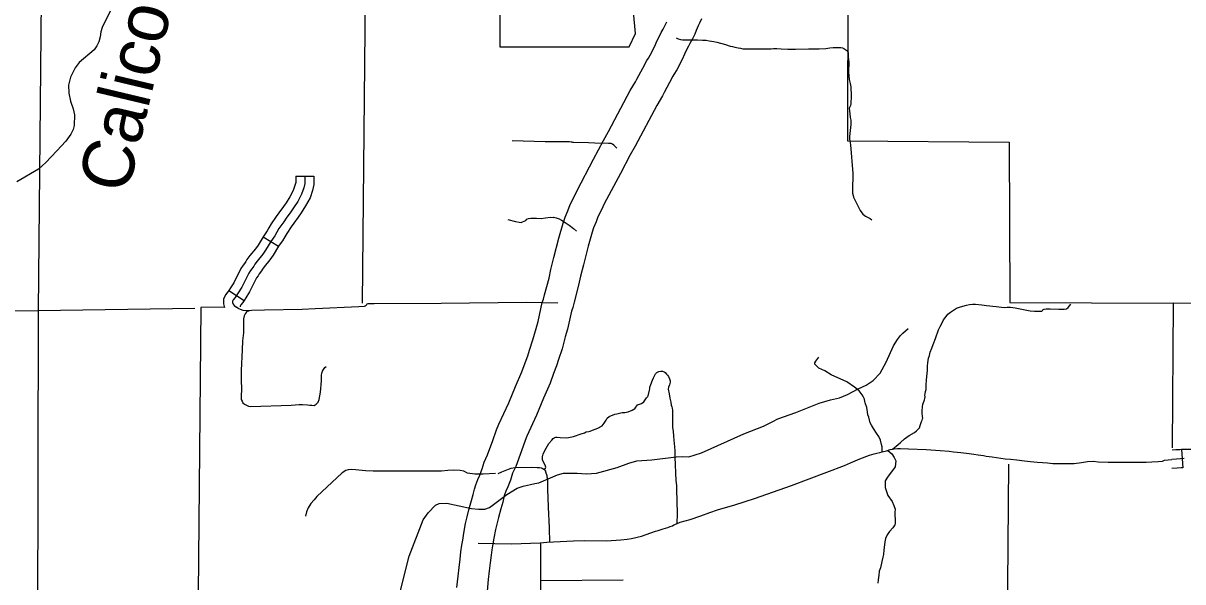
# Model space of a CAD drawing. Extents: x 1377389 to 1380723, y 1168351 to 1170484.
# Drawn here: x 1378680.8 to 1378871.6, y 1168997.5 to 1169089.4 of the extents above; entities that cross this region are included whole.
import ezdxf

# ---------------------------------------------------------------- set-up
doc = ezdxf.new("R2010")
doc.units = 0
doc.layers.add('B_Fill', color=7, linetype='Continuous')

msp = doc.modelspace()

# ---------------------------------------------------------------- linework, layer by layer
at = {"layer": 'B_Fill'}
for p, q in [((1378725.61, 1169064.2), (1378728.61, 1169064.2)), ((1378720.23, 1169054.24), (1378722.8, 1169052.7)), ((1378714.6, 1169045.4), (1378717.12, 1169043.77)), ((1378871.37, 1169019.22), (1378871.59, 1169016.23))]:
    msp.add_line(p, q, dxfattribs=at)
for points in [[(1378737.66, 1169202.93), (1378737.6, 1169150.04), (1378736.52, 1169043.33)], [(1378842.99, 1169154.28), (1378843.04, 1169149.86), (1378843.04, 1169123.02), (1378816.55, 1169123.12), (1378816.4, 1169069.98), (1378843.01, 1169069.78), (1378843.12, 1169043.4)], [(1378684.26, 1169150.09), (1378683.24, 1169042.11)], [(1378695.06, 1169091.31), (1378693.76, 1169088.66), (1378693.52, 1169087.95), (1378693.44, 1169087.09), (1378693.23, 1169086.27), (1378692.89, 1169085.64), (1378692.45, 1169084.99), (1378689.96, 1169082.87), (1378689.32, 1169082), (1378688.57, 1169080.5), (1378688.21, 1169079.15), (1378688.28, 1169077.83), (1378688.56, 1169076.55), (1378689.01, 1169075.26), (1378689.19, 1169074.27), (1378689.13, 1169072.52), (1378689.01, 1169071.86), (1378688.59, 1169071.09), (1378687.77, 1169069.95), (1378686.31, 1169068.38), (1378684.5, 1169066.46), (1378683.27, 1169065.37), (1378679.7, 1169063.29)], [(1378780.67, 1169078.26), (1378781.52, 1169079.69), (1378781.72, 1169080.16), (1378782.71, 1169081.97), (1378783.37, 1169083.21), (1378783.64, 1169083.61), (1378783.94, 1169084.12), (1378784.7, 1169085.57), (1378785.06, 1169086.39), (1378785.49, 1169087.23), (1378785.76, 1169087.85), (1378786.07, 1169088.4), (1378786.45, 1169089.12), (1378786.7, 1169089.6)], [(1378792.36, 1169090.09), (1378792.04, 1169089.34), (1378791.83, 1169088.92), (1378791.67, 1169088.54), (1378791.5, 1169088.15), (1378791.27, 1169087.54), (1378790.88, 1169086.81), (1378790.47, 1169086.01), (1378790.24, 1169085.6), (1378790, 1169085.08), (1378789.58, 1169084.24), (1378789.21, 1169083.41), (1378788.31, 1169081.68), (1378787.85, 1169080.92), (1378787.65, 1169080.62), (1378787.11, 1169079.61), (1378786.22, 1169077.96), (1378785.98, 1169077.41), (1378785.03, 1169075.81)], [(1378788.2, 1169086.93), (1378788.57, 1169086.8), (1378788.92, 1169086.7), (1378789.27, 1169086.63), (1378789.82, 1169086.61), (1378791, 1169086.61), (1378791.74, 1169086.61), (1378792.53, 1169086.59), (1378793.15, 1169086.54), (1378793.64, 1169086.47), (1378794.03, 1169086.41), (1378794.42, 1169086.33), (1378794.89, 1169086.22), (1378796.36, 1169085.83), (1378797.13, 1169085.6), (1378797.5, 1169085.52), (1378797.89, 1169085.41), (1378798.42, 1169085.3), (1378798.82, 1169085.23), (1378799.21, 1169085.16), (1378799.79, 1169085.13), (1378801.11, 1169085.13), (1378802.29, 1169085.14), (1378803.84, 1169085.16), (1378804.23, 1169085.18), (1378804.8, 1169085.18), (1378805.48, 1169085.14), (1378806.61, 1169085.07), (1378807.83, 1169085.11), (1378809.99, 1169085.13), (1378811.74, 1169085.14), (1378812.85, 1169085.2), (1378813.48, 1169085.29), (1378814.08, 1169085.34), (1378814.72, 1169085.36), (1378815.03, 1169085.36), (1378815.3, 1169085.34), (1378815.58, 1169085.29), (1378815.79, 1169085.2), (1378815.97, 1169085.11), (1378816.16, 1169084.98), (1378816.28, 1169084.88), (1378816.37, 1169084.81), (1378816.4, 1169084.79), (1378816.41, 1169084.77), (1378816.42, 1169084.76), (1378816.44, 1169084.71)], [(1378816.44, 1169084.71), (1378816.47, 1169084.64), (1378816.52, 1169084.52), (1378816.54, 1169084.39), (1378816.53, 1169083.85), (1378816.63, 1169082.96), (1378816.58, 1169081.29), (1378816.69, 1169080.12), (1378816.88, 1169079.45), (1378816.97, 1169078.89), (1378817.04, 1169077.41), (1378816.95, 1169076.11), (1378816.9, 1169075.83), (1378816.75, 1169075.5), (1378816.68, 1169075.32), (1378816.76, 1169075.02), (1378816.83, 1169073.86), (1378816.94, 1169073.43), (1378816.99, 1169073.19), (1378816.94, 1169072.71), (1378816.73, 1169070.72), (1378816.73, 1169070.26), (1378816.79, 1169069.98)], [(1378752.15, 1168996.53), (1378752.33, 1168998.4), (1378752.49, 1168999.84), (1378752.65, 1169001.19), (1378752.8, 1169002.4), (1378752.92, 1169003.49), (1378753.09, 1169004.33), (1378753.3, 1169005.5), (1378753.57, 1169007.06), (1378753.83, 1169008.15), (1378754.12, 1169009.34), (1378754.53, 1169010.83), (1378754.82, 1169011.81), (1378755.02, 1169012.73), (1378755.25, 1169013.4), (1378755.56, 1169014.29), (1378755.91, 1169015.01), (1378756.18, 1169015.77), (1378756.28, 1169016.08), (1378756.64, 1169017.18), (1378757.18, 1169018.37), (1378758.06, 1169020.72), (1378758.67, 1169022.48), (1378759.05, 1169023.43), (1378760.66, 1169026.92), (1378761.79, 1169029.61), (1378762.82, 1169032.02), (1378763.37, 1169033.51), (1378763.79, 1169034.63), (1378764.09, 1169035.58), (1378764.65, 1169037.26), (1378765.17, 1169039.13), (1378765.51, 1169040.27), (1378766.18, 1169043.39), (1378766.39, 1169043.98), (1378766.55, 1169044.7), (1378767.31, 1169047.43), (1378767.61, 1169048.86), (1378768.1, 1169050.84), (1378768.89, 1169053.98), (1378769.63, 1169056.49), (1378769.95, 1169057.43), (1378770.39, 1169058.52), (1378770.77, 1169059.52), (1378771.43, 1169060.82), (1378771.91, 1169061.86), (1378774.64, 1169066.99), (1378776.27, 1169070.08), (1378777.08, 1169071.52), (1378780.67, 1169078.26)], [(1378785.03, 1169075.81), (1378781.47, 1169069.12), (1378780.66, 1169067.68), (1378779.05, 1169064.65), (1378776.39, 1169059.64), (1378775.93, 1169058.64), (1378775.34, 1169057.48), (1378775.05, 1169056.7), (1378774.64, 1169055.69), (1378774.39, 1169054.97), (1378773.72, 1169052.66), (1378772.95, 1169049.63), (1378772.49, 1169047.74), (1378772.17, 1169046.24), (1378771.41, 1169043.48), (1378771.2, 1169042.57), (1378771, 1169042.01), (1378770.36, 1169039.02), (1378769.97, 1169037.75), (1378769.44, 1169035.81), (1378768.85, 1169034.03), (1378768.52, 1169032.99), (1378768.05, 1169031.76), (1378767.46, 1169030.17), (1378766.4, 1169027.66), (1378765.23, 1169024.91), (1378763.65, 1169021.44), (1378763.35, 1169020.72), (1378762.76, 1169019.03), (1378761.81, 1169016.46), (1378761.3, 1169015.35), (1378761.04, 1169014.56), (1378760.93, 1169014.19), (1378760.52, 1169013.07), (1378760.19, 1169012.38), (1378759.98, 1169011.76), (1378759.84, 1169011.38), (1378759.67, 1169010.57), (1378759.34, 1169009.46), (1378758.96, 1169008.07), (1378758.68, 1169006.96), (1378758.47, 1169006.06), (1378758.22, 1169004.64), (1378758.01, 1169003.4), (1378757.87, 1169002.72), (1378757.77, 1169001.83), (1378757.61, 1169000.58), (1378757.46, 1168999.27), (1378757.3, 1168997.88), (1378757.12, 1168995.93)], [(1378778.43, 1169068.82), (1378777.94, 1169069.29), (1378777.73, 1169069.47), (1378777.54, 1169069.55), (1378777.38, 1169069.58), (1378777.1, 1169069.58), (1378774.84, 1169069.65), (1378773.78, 1169069.66), (1378771.33, 1169069.75), (1378771.22, 1169069.76), (1378771.11, 1169069.77), (1378770.95, 1169069.81), (1378770.69, 1169069.85), (1378770.35, 1169069.87), (1378769.46, 1169069.83), (1378766.64, 1169069.85), (1378761.25, 1169069.99)], [(1378816.79, 1169069.98), (1378816.93, 1169069.35), (1378817.29, 1169064.61), (1378817.26, 1169061.82), (1378817.26, 1169061.4), (1378817.32, 1169061.02), (1378817.4, 1169060.72), (1378818.52, 1169058.54), (1378818.92, 1169057.95), (1378819.38, 1169057.61), (1378820.16, 1169057.21), (1378820.42, 1169057)], [(1378725.61, 1169064.2), (1378725.61, 1169063.17), (1378725.49, 1169062.68), (1378725.2, 1169061.86), (1378724.64, 1169060.8), (1378724.02, 1169059.82), (1378723.59, 1169059.22), (1378722.84, 1169058.18), (1378722.4, 1169057.56), (1378721.58, 1169056.37), (1378721.19, 1169055.69)], [(1378727.11, 1169064.2), (1378727.11, 1169063), (1378726.93, 1169062.25), (1378726.58, 1169061.25), (1378725.94, 1169060.05), (1378725.27, 1169058.98), (1378724.8, 1169058.34), (1378724.06, 1169057.31), (1378723.63, 1169056.71), (1378722.85, 1169055.57), (1378722.18, 1169054.4), (1378721.52, 1169053.47)], [(1378728.61, 1169064.2), (1378728.61, 1169062.82), (1378728.38, 1169061.82), (1378727.96, 1169060.65), (1378727.24, 1169059.29), (1378726.51, 1169058.14), (1378726.02, 1169057.46), (1378725.28, 1169056.44), (1378724.86, 1169055.85), (1378724.12, 1169054.77), (1378723.79, 1169054.2)], [(1378760.49, 1169057.06), (1378761.77, 1169056.73), (1378762.39, 1169056.62), (1378762.72, 1169056.6), (1378762.94, 1169056.68), (1378763.19, 1169056.78), (1378763.46, 1169056.93), (1378763.67, 1169057.1), (1378763.92, 1169057.26), (1378764.29, 1169057.3), (1378765.24, 1169057.28), (1378765.98, 1169057.24), (1378766.69, 1169057.32), (1378767.53, 1169057.45), (1378767.99, 1169057.41), (1378768.01, 1169057.43), (1378768.46, 1169057.34), (1378768.96, 1169057.18), (1378769.37, 1169056.97), (1378769.95, 1169056.6), (1378770.59, 1169056.13), (1378771.32, 1169055.57), (1378771.83, 1169055.16)], [(1378721.19, 1169055.69), (1378720.91, 1169055.21), (1378720.23, 1169054.24)], [(1378720.23, 1169054.24), (1378719.41, 1169052.86), (1378718.98, 1169052.27), (1378718.07, 1169051.15), (1378717.58, 1169050.5), (1378717.41, 1169050.17), (1378717.17, 1169049.84), (1378716.96, 1169049.53), (1378716.59, 1169049.01), (1378715.42, 1169046.66), (1378714.87, 1169045.82), (1378714.6, 1169045.4)], [(1378721.52, 1169053.47), (1378720.66, 1169052.03), (1378720.17, 1169051.36), (1378719.25, 1169050.23), (1378718.86, 1169049.71), (1378718.7, 1169049.4), (1378718.4, 1169048.97), (1378718.18, 1169048.67), (1378717.88, 1169048.24), (1378716.72, 1169045.92), (1378716.13, 1169045), (1378715.65, 1169044.26), (1378715.3, 1169043.85), (1378715.2, 1169043.63), (1378715.2, 1169043.43), (1378715.26, 1169043.27), (1378715.3, 1169043.14), (1378715.46, 1169042.94), (1378715.85, 1169042.65)], [(1378723.79, 1169054.2), (1378723.44, 1169053.58), (1378722.74, 1169052.6)], [(1378722.8, 1169052.7), (1378721.91, 1169051.2), (1378721.36, 1169050.44), (1378720.43, 1169049.3), (1378720.13, 1169048.91), (1378719.99, 1169048.62), (1378719.62, 1169048.11), (1378719.41, 1169047.8), (1378719.17, 1169047.46), (1378718.03, 1169045.17), (1378717.39, 1169044.18), (1378717.12, 1169043.77)], [(1378714.6, 1169045.4), (1378714.44, 1169045.15), (1378714.03, 1169044.66), (1378713.7, 1169043.97), (1378713.7, 1169043.17), (1378713.84, 1169042.77), (1378713.9, 1169042.62)], [(1378717.12, 1169043.77), (1378716.91, 1169043.44), (1378716.56, 1169043.03), (1378716.46, 1169042.82), (1378716.46, 1169042.7)], [(1378578.22, 1169041.82), (1378683.24, 1169042.11)], [(1378713.89, 1169042.63), (1378709.98, 1169042.59), (1378709.33, 1168971.91), (1378682.9, 1168971.87), (1378682.95, 1168989.04), (1378655.79, 1168988.68)], [(1378683.24, 1169042.11), (1378683.13, 1168989.64)], [(1378683.24, 1169042.11), (1378709.01, 1169042.47)], [(1378717.7, 1169042.06), (1378717.94, 1169042.07), (1378717.39, 1169042.06), (1378716.96, 1169042.12), (1378716.5, 1169042.24), (1378716.14, 1169042.42), (1378715.85, 1169042.65)], [(1378718.37, 1169042.09), (1378717.94, 1169042.07), (1378717.76, 1169042.03), (1378717.57, 1169041.9), (1378717.47, 1169041.77), (1378717.3, 1169041.57), (1378717.19, 1169041.35), (1378717.11, 1169041.2), (1378717.01, 1169040.72), (1378716.99, 1169040.43), (1378716.99, 1169039.26), (1378717.01, 1169038.44), (1378716.85, 1169037.13), (1378716.77, 1169035.61), (1378716.64, 1169032.22), (1378716.63, 1169031.28), (1378716.61, 1169030.45), (1378716.69, 1169029.33), (1378716.64, 1169027.83), (1378716.64, 1169027.44), (1378716.78, 1169027.17), (1378716.91, 1169026.91), (1378717.17, 1169026.67), (1378717.6, 1169026.48), (1378717.83, 1169026.38), (1378718.2, 1169026.31), (1378724.87, 1169026.54), (1378726.16, 1169026.64), (1378726.72, 1169026.64), (1378727.55, 1169026.58), (1378727.91, 1169026.51), (1378728.27, 1169026.51), (1378728.64, 1169026.48), (1378729, 1169026.71), (1378729.3, 1169027.01), (1378729.46, 1169027.47), (1378729.66, 1169028.66), (1378729.83, 1169030.54), (1378729.83, 1169031.46), (1378729.89, 1169031.78), (1378730.04, 1169032.12), (1378730.19, 1169032.42), (1378730.41, 1169032.7), (1378730.6, 1169032.9)], [(1378768.74, 1169043.28), (1378763.57, 1169043.4), (1378749.54, 1169043.25), (1378738.51, 1169043.19), (1378737.84, 1169043.19), (1378737.5, 1169043.19), (1378737.32, 1169043.13), (1378737.2, 1169042.94), (1378737.04, 1169042.82), (1378736.86, 1169042.76), (1378735.97, 1169042.7), (1378728.79, 1169042.36), (1378726.68, 1169042.24), (1378720.45, 1169042.15), (1378718.37, 1169042.09)], [(1378823.8, 1169019.31), (1378824.73, 1169020.05), (1378825.14, 1169020.4), (1378825.82, 1169021), (1378826.55, 1169021.54), (1378827.43, 1169022.03), (1378827.76, 1169022.31), (1378828.06, 1169022.57), (1378828.24, 1169022.78), (1378828.39, 1169023.16), (1378828.58, 1169023.86), (1378828.68, 1169024.05), (1378828.78, 1169024.26), (1378828.79, 1169024.41), (1378828.76, 1169024.69), (1378828.72, 1169025.2), (1378828.69, 1169025.53), (1378828.72, 1169025.79), (1378828.73, 1169026.05), (1378828.76, 1169026.31), (1378828.82, 1169026.63), (1378828.93, 1169026.98), (1378829.01, 1169027.25), (1378829.06, 1169027.42), (1378829.13, 1169027.63), (1378829.17, 1169027.88), (1378829.16, 1169028.18), (1378829.19, 1169028.42), (1378829.27, 1169028.75), (1378829.37, 1169029.09), (1378829.37, 1169029.49), (1378829.37, 1169029.83), (1378829.39, 1169030.67), (1378829.5, 1169031.74), (1378829.57, 1169032.23), (1378829.59, 1169032.95), (1378829.65, 1169033.5), (1378829.76, 1169034.27), (1378829.9, 1169034.71), (1378830.03, 1169035.26), (1378830.28, 1169035.9), (1378830.5, 1169036.53), (1378830.89, 1169037.47), (1378831.41, 1169038.9), (1378831.65, 1169039.45), (1378831.93, 1169039.94), (1378832.23, 1169040.55), (1378832.64, 1169041.12), (1378832.95, 1169041.48), (1378833.36, 1169041.81), (1378833.85, 1169042.17), (1378834.35, 1169042.47), (1378834.84, 1169042.64), (1378835.37, 1169042.83), (1378836, 1169043), (1378836.49, 1169043.08), (1378836.96, 1169043.13), (1378837.48, 1169043.13), (1378838.53, 1169043.05), (1378839.27, 1169042.94), (1378840.89, 1169042.75), (1378842.21, 1169042.61), (1378842.68, 1169042.64), (1378843.25, 1169042.64), (1378844, 1169042.53), (1378845.92, 1169042.14), (1378846.5, 1169042.06), (1378847.18, 1169042), (1378847.65, 1169042), (1378848.12, 1169041.98), (1378848.37, 1169042), (1378848.48, 1169042.09), (1378848.57, 1169042.23), (1378848.78, 1169042.32), (1378849.11, 1169042.38), (1378849.74, 1169042.38), (1378851.19, 1169042.34), (1378852.07, 1169042.32), (1378852.44, 1169042.36), (1378852.71, 1169042.57), (1378853.18, 1169043.13)], [(1378843.12, 1169043.4), (1378870.03, 1169043.29)], [(1378870.03, 1169043.29), (1378869.84, 1169019.51)], [(1378897.14, 1169043.18), (1378870.03, 1169043.29)], [(1378784.22, 1169017.56), (1378788.23, 1169018.05), (1378789.27, 1169018.07), (1378790.31, 1169018.05), (1378792.39, 1169018.71), (1378799.37, 1169021.8), (1378802.61, 1169023.07), (1378804.15, 1169023.83), (1378804.96, 1169024.28), (1378807.9, 1169025.33), (1378811.77, 1169026.86), (1378813.64, 1169027.42), (1378815.08, 1169027.75), (1378816.42, 1169028.29), (1378818.19, 1169029.23), (1378819.49, 1169029.84), (1378820.65, 1169030.61), (1378821.78, 1169031.78), (1378822.8, 1169033.58), (1378823.98, 1169036.28), (1378824.66, 1169037.32), (1378825.16, 1169037.97), (1378825.52, 1169038.35), (1378826.38, 1169039.14)], [(1378822.11, 1169018.83), (1378822.11, 1169019.69), (1378822, 1169020.08), (1378821.83, 1169020.75), (1378821.56, 1169021.36), (1378821.17, 1169021.91), (1378820.67, 1169022.68), (1378820.34, 1169023.24), (1378820.12, 1169023.63), (1378819.9, 1169024.54), (1378819.77, 1169024.95), (1378819.7, 1169025.43), (1378819.57, 1169026.14), (1378819.34, 1169026.9), (1378819.24, 1169027.13), (1378819.19, 1169027.49), (1378819.04, 1169027.82), (1378818.83, 1169028.23), (1378818.33, 1169028.89), (1378817.59, 1169029.5), (1378816.29, 1169030.34), (1378813.72, 1169031.51), (1378812.68, 1169032.17), (1378811.72, 1169032.63), (1378811.34, 1169032.96), (1378811.03, 1169033.29), (1378811.06, 1169033.49), (1378811.18, 1169033.75), (1378811.69, 1169034.41)], [(1378784.05, 1169029.91), (1378784.31, 1169030.65), (1378784.48, 1169031), (1378784.63, 1169031.37), (1378784.83, 1169031.67), (1378785.05, 1169031.91), (1378785.35, 1169032.06), (1378785.72, 1169032.11), (1378785.99, 1169032.11), (1378786.25, 1169032.01), (1378786.41, 1169031.88), (1378786.6, 1169031.64), (1378786.78, 1169031.49), (1378786.95, 1169031.22), (1378787.11, 1169030.88), (1378787.22, 1169030.51), (1378787.25, 1169030.31), (1378787.11, 1169029.9), (1378786.95, 1169029.5), (1378786.88, 1169029.16), (1378787.05, 1169028.42), (1378787.15, 1169027.68), (1378787.35, 1169027.03), (1378787.42, 1169026.53), (1378787.52, 1169026.28), (1378787.58, 1169026.05), (1378787.6, 1169025.68), (1378787.59, 1169023.37), (1378787.63, 1169022.88), (1378787.71, 1169022.24), (1378787.78, 1169021.43), (1378787.83, 1169020.77), (1378787.93, 1169019.68), (1378787.99, 1169019), (1378787.99, 1169017.99), (1378788.19, 1169014.14), (1378788.27, 1169013.3), (1378788.3, 1169013.06), (1378788.3, 1169012.73), (1378788.36, 1169008.69), (1378788.31, 1169007.04)], [(1378766.46, 1169015.95), (1378766.57, 1169016.03), (1378766.73, 1169016.17), (1378766.75, 1169016.35), (1378766.73, 1169016.49), (1378766.51, 1169016.97), (1378766.3, 1169017.4), (1378766.24, 1169017.54), (1378766.22, 1169017.71), (1378766.24, 1169018.16), (1378766.26, 1169018.27), (1378766.31, 1169018.49), (1378766.62, 1169019.07), (1378767.26, 1169020.25), (1378767.74, 1169020.79), (1378767.99, 1169021.05), (1378768.15, 1169021.17), (1378768.27, 1169021.23), (1378768.42, 1169021.26), (1378768.66, 1169021.27), (1378769.14, 1169021.22), (1378770.21, 1169021.16), (1378771.34, 1169021.38), (1378772.6, 1169021.83), (1378773.15, 1169022), (1378773.43, 1169022.13), (1378773.82, 1169022.22), (1378774.08, 1169022.28), (1378774.47, 1169022.4), (1378775.31, 1169022.77), (1378776.06, 1169023.15), (1378776.38, 1169023.58), (1378776.7, 1169024.06), (1378776.86, 1169024.38), (1378777.18, 1169024.64), (1378778.15, 1169025.03), (1378778.47, 1169025.12), (1378778.9, 1169025.24), (1378779.31, 1169025.33), (1378779.76, 1169025.35), (1378780.3, 1169025.46), (1378780.99, 1169025.72), (1378781.27, 1169025.85), (1378781.42, 1169025.95), (1378781.56, 1169026.19), (1378781.75, 1169026.44), (1378781.88, 1169026.57), (1378782.21, 1169026.71), (1378782.53, 1169026.79), (1378782.91, 1169027.09), (1378783.13, 1169027.39), (1378783.35, 1169027.71), (1378783.54, 1169027.93), (1378783.62, 1169028.09), (1378783.81, 1169028.99), (1378783.89, 1169029.23), (1378783.86, 1169029.47), (1378784.05, 1169029.91)], [(1378784.81, 1169005.8), (1378785.28, 1169005.93), (1378785.74, 1169006.06), (1378786.08, 1169006.18), (1378786.47, 1169006.29), (1378786.87, 1169006.43), (1378787.25, 1169006.57), (1378787.59, 1169006.7), (1378787.86, 1169006.82), (1378788.27, 1169007.03), (1378788.89, 1169007.28), (1378789.69, 1169007.5), (1378790.5, 1169007.73), (1378792.26, 1169008.34), (1378793.78, 1169008.89), (1378795.01, 1169009.3), (1378797.9, 1169010.15), (1378801.09, 1169011.17), (1378807.21, 1169013.29), (1378815.9, 1169016.58), (1378816.93, 1169017.06), (1378818.47, 1169017.69), (1378820.03, 1169018.28), (1378820.42, 1169018.43), (1378820.78, 1169018.54), (1378821.22, 1169018.61), (1378821.72, 1169018.72), (1378822.14, 1169018.84), (1378822.83, 1169019.01), (1378823.45, 1169019.23), (1378824.11, 1169019.37), (1378824.65, 1169019.4), (1378825.14, 1169019.39), (1378826.47, 1169019.35), (1378829.37, 1169019.21), (1378831.68, 1169019.07), (1378833.15, 1169018.96), (1378833.87, 1169018.87), (1378835.04, 1169018.72), (1378836.45, 1169018.59), (1378837.21, 1169018.49), (1378837.93, 1169018.38), (1378838.79, 1169018.24), (1378839.25, 1169018.15), (1378840.2, 1169018.03), (1378842.38, 1169017.72), (1378843.22, 1169017.66), (1378844.26, 1169017.54), (1378845.56, 1169017.39), (1378846.51, 1169017.27), (1378847.65, 1169017.17), (1378848.49, 1169017.08), (1378849.31, 1169017.02), (1378850.21, 1169016.93), (1378850.91, 1169016.93), (1378851.66, 1169016.92), (1378852.35, 1169016.92), (1378853.74, 1169016.96), (1378854.94, 1169017.09), (1378855.9, 1169017.25), (1378856.87, 1169017.32), (1378857.69, 1169017.23), (1378859.32, 1169017.16), (1378861.81, 1169017.16), (1378864.39, 1169017.14), (1378865.59, 1169017.16), (1378866.5, 1169017.21), (1378867.52, 1169017.25), (1378868.24, 1169017.34), (1378868.56, 1169017.48), (1378869.78, 1169017.61)], [(1378823.03, 1169019.09), (1378823.69, 1169018.54), (1378824.08, 1169017.92), (1378824.35, 1169017.37), (1378824.31, 1169016.9), (1378824.24, 1169016.36), (1378822.99, 1169014.68), (1378822.64, 1169014.06), (1378822.64, 1169012.97), (1378823.07, 1169011.68), (1378823.77, 1169010.71), (1378824.04, 1169010.05), (1378824.27, 1169009.42), (1378824.2, 1169008.88), (1378824.2, 1169008.41), (1378824.27, 1169007.71), (1378824.27, 1169007.32), (1378824.27, 1169007.09), (1378824.2, 1169006.85), (1378823.85, 1169006.38), (1378823.3, 1169005.76), (1378822.95, 1169005.18), (1378822.68, 1169004.59), (1378822.56, 1169004.05), (1378822.48, 1169003.58), (1378822.37, 1169002.72), (1378822.33, 1169001.98), (1378822.25, 1169001.51), (1378822.06, 1169000.81), (1378821.82, 1168999.8), (1378821.63, 1168999.22), (1378821.55, 1168998.55), (1378821.47, 1168997.81), (1378821.39, 1168997.23)], [(1378871.37, 1169019.22), (1378871.08, 1169019.2), (1378870.46, 1169019.16), (1378869.84, 1169019.12)], [(1378882.04, 1169019.32), (1378881.92, 1169019.32), (1378881.41, 1169019.28), (1378881.05, 1169019.25), (1378874.01, 1169019.23), (1378872.65, 1169019.25), (1378871.74, 1169019.25), (1378871.37, 1169019.22)], [(1378771.94, 1169015.32), (1378773.44, 1169015.26), (1378775.13, 1169015.37), (1378778.51, 1169016.29), (1378780.42, 1169017.01), (1378781.73, 1169017.36), (1378784.22, 1169017.56)], [(1378871.8, 1169017.75), (1378871.19, 1169017.7), (1378870.55, 1169017.66), (1378869.78, 1169017.61)], [(1378758.5, 1169015.28), (1378756.43, 1169015.18), (1378755.07, 1169015.18), (1378753.87, 1169015.37), (1378753.29, 1169015.66), (1378752.66, 1169015.76), (1378751.64, 1169015.86), (1378750.63, 1169015.81), (1378749.62, 1169015.66), (1378738.36, 1169015.66), (1378737.1, 1169015.71), (1378735.46, 1169015.88), (1378734.79, 1169015.97), (1378734.25, 1169015.88), (1378733.83, 1169015.76), (1378733.24, 1169015.42), (1378729.09, 1169011.52), (1378728.63, 1169010.97), (1378728.12, 1169010.34), (1378727.66, 1169009.63), (1378727.37, 1169008.96), (1378727.24, 1169008.29)], [(1378742.56, 1168994.93), (1378744.29, 1169001.67), (1378746.59, 1169007.67), (1378747.42, 1169008.81), (1378748.59, 1169010.08), (1378749.22, 1169010.35), (1378750.46, 1169010.4), (1378754.51, 1169009.55), (1378755.71, 1169009.4), (1378756.75, 1169009.44), (1378757.5, 1169009.68), (1378760.34, 1169011.82), (1378762.06, 1169012.88), (1378763.03, 1169013.2), (1378764.95, 1169013.67), (1378765.61, 1169013.74), (1378768.71, 1169015.09), (1378769.65, 1169015.35), (1378771.94, 1169015.32)], [(1378758.9, 1169015.28), (1378759.53, 1169015.57), (1378760.05, 1169015.79), (1378760.6, 1169016.01), (1378761.05, 1169016.16), (1378761.69, 1169016.26), (1378764.44, 1169016.31), (1378765.37, 1169016.29), (1378765.71, 1169016.28), (1378766, 1169016.23), (1378766.19, 1169016.14), (1378766.45, 1169016), (1378766.57, 1169015.89), (1378766.69, 1169015.69), (1378766.74, 1169015.54), (1378766.79, 1169015.4), (1378766.87, 1169015.15), (1378766.91, 1169014.98), (1378766.96, 1169014.76), (1378767, 1169014.6), (1378767.01, 1169014.48), (1378767.05, 1169014.32), (1378767.07, 1169014.06), (1378767.07, 1169012.69), (1378767.18, 1169009.78), (1378767.2, 1169008.53), (1378767.27, 1169007.56), (1378767.31, 1169006.31), (1378767.4, 1169004.01)], [(1378842.92, 1169016.8), (1378842.69, 1168990.3)], [(1378871.59, 1169016.23), (1378871.3, 1169016.21), (1378870.65, 1169016.16), (1378869.81, 1169016.11)], [(1378755.66, 1169003.81), (1378761.13, 1169003.74), (1378765.84, 1169003.86), (1378766.96, 1169003.98), (1378771.31, 1169004.22), (1378773.13, 1169004.29), (1378776.78, 1169004.24), (1378779.13, 1169004.36), (1378780.13, 1169004.48), (1378780.87, 1169004.6), (1378782.54, 1169004.99), (1378784.81, 1169005.8)], [(1378766.03, 1168991.31), (1378765.94, 1168997.68), (1378765.92, 1169003.59), (1378765.9, 1169003.86)], [(1378765.94, 1168997.7), (1378779.48, 1168997.81)]]:
    msp.add_lwpolyline(points, dxfattribs=at)
msp.add_lwpolyline([(1378754.45, 1169117.28), (1378755.97, 1169107.13), (1378755.3, 1169091.74), (1378756.65, 1169090.89), (1378759.19, 1169090.89), (1378759.19, 1169085.48), (1378780.51, 1169085.48), (1378781.52, 1169087.68), (1378781.18, 1169091.23), (1378781.69, 1169095.29), (1378783.55, 1169098.51), (1378784.73, 1169100.87), (1378786.43, 1169103.41), (1378787.44, 1169106.12), (1378788.29, 1169108.32), (1378789.81, 1169110.18), (1378790.15, 1169111.36), (1378789.47, 1169112.21), (1378784.23, 1169112.21), (1378785.41, 1169114.58), (1378785.58, 1169116.1), (1378784.88, 1169117.27)], close=True, dxfattribs=at)

# ---------------------------------------------------------------- texts
msp.add_text('Calico', height=8.448, rotation=76.6149, dxfattribs=at).set_placement((1378697.95, 1169061.1))

doc.saveas('drawing.dxf')
